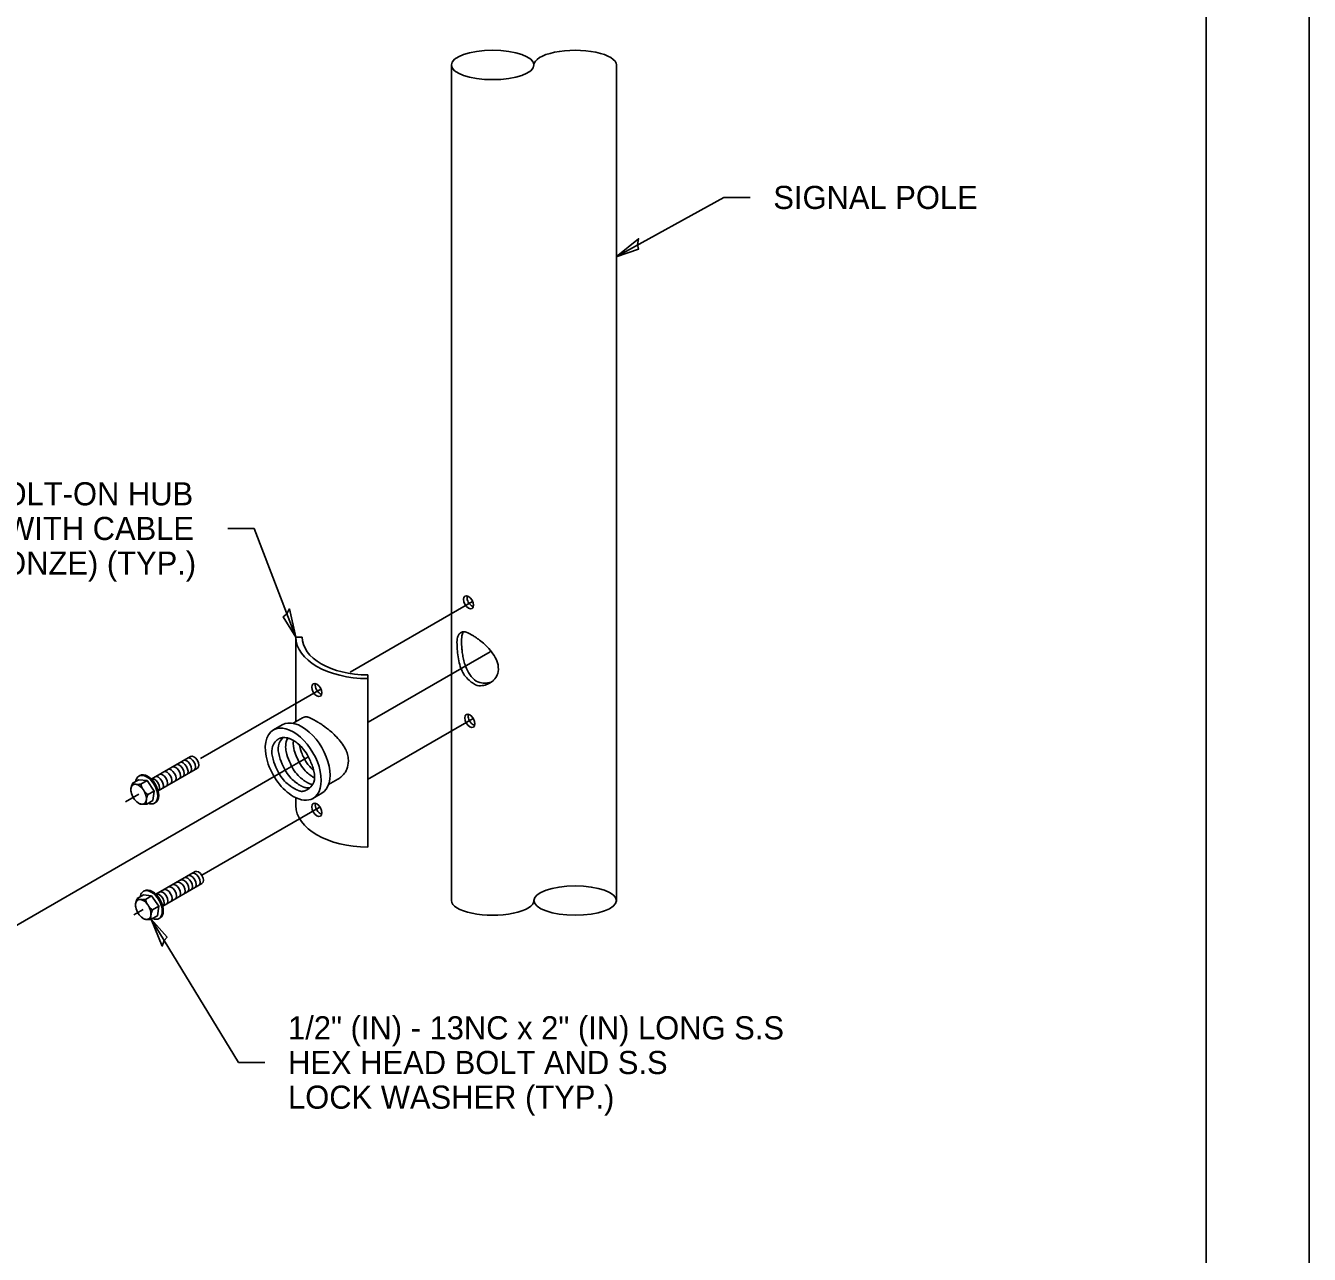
# Model space of a CAD drawing. Extents: x 99999.1 to 100016.1, y 99999.7 to 100010.7.
# Drawn here: x 100012.175 to 100016.062, y 100003.419 to 100007.14 of the extents above; entities that cross this region are included whole.
import ezdxf

# ---------------------------------------------------------------- set-up
doc = ezdxf.new("R2010")
doc.units = 0
for name, color, linetype in [('Level 15', 7, 'Continuous'), ('Level 2', 7, 'Continuous'), ('Level 20', 7, 'Continuous'), ('SH_GI_PlotLimits', 7, 'Continuous'), ('SH_GI_SheetBorder', 7, 'Continuous')]:
    doc.layers.add(name, color=color, linetype=linetype)

msp = doc.modelspace()

# ---------------------------------------------------------------- linework, layer by layer
at = {"layer": 'Level 15'}
for p, q in [((100013.963, 100006.4396), (100014.2892, 100006.6198)), ((100014.3692, 100006.6198), (100014.2892, 100006.6198)), ((100012.7872, 100005.6172), (100012.8672, 100005.6172)), ((100012.993, 100005.2884), (100012.8672, 100005.6172)), ((100013.5286, 100005.3962), (100013.1572, 100005.1818)), ((100013.5813, 100005.2435), (100013.2122, 100005.0304)), ((100013.5302, 100005.0419), (100013.2102, 100004.8571)), ((100013.0292, 100004.9248), (100012.9521, 100004.8802)), ((100012.9536, 100004.8809), (100012.0572, 100004.3633)), ((100012.5554, 100004.4334), (100012.8192, 100003.9999)), ((100012.8992, 100003.9998), (100012.8192, 100003.9998))]:
    msp.add_line(p, q, dxfattribs=at)
for points in [[(100013.963, 100006.4396), (100014.0311, 100006.4944), (100014.0279, 100006.4771), (100014.0311, 100006.4635)], [(100012.993, 100005.2884), (100012.9543, 100005.3493), (100012.9652, 100005.358), (100012.9734, 100005.3736)], [(100012.5554, 100004.4334), (100012.6033, 100004.3794), (100012.5939, 100004.369), (100012.5883, 100004.3524)]]:
    msp.add_lwpolyline(points, close=True, dxfattribs=at)
at = {"layer": 'Level 2'}
for p, q in [((100013.4642, 100005.6753), (100013.4642, 100007.0209)), ((100013.9642, 100004.4871), (100013.9642, 100007.0209)), ((100013.9642, 100004.809), (100013.9642, 100005.9662)), ((100013.4642, 100004.4901), (100013.4642, 100005.6753)), ((100013.5158, 100005.3937), (100013.5158, 100005.3937)), ((100012.993, 100005.0317), (100012.993, 100005.2884)), ((100013.0119, 100005.2884), (100012.993, 100005.2884)), ((100013.2109, 100005.1626), (100013.2109, 100005.1735)), ((100013.2109, 100005.1626), (100013.2109, 100004.6524)), ((100012.7043, 100004.9203), (100013.0683, 100005.1305)), ((100013.0129, 100005.0432), (100012.9851, 100005.0271)), ((100012.952, 100005.0226), (100012.9253, 100005.0071)), ((100012.6742, 100004.9269), (100012.5552, 100004.8582)), ((100012.576, 100004.8223), (100012.6949, 100004.891)), ((100012.5173, 100004.8562), (100012.4988, 100004.8455)), ((100012.5173, 100004.8562), (100012.5424, 100004.8535)), ((100012.5205, 100004.869), (100012.5175, 100004.8673)), ((100012.5424, 100004.8535), (100012.5239, 100004.8427)), ((100012.5424, 100004.8535), (100012.5637, 100004.8219)), ((100013.0922, 100004.8415), (100013.1201, 100004.8575)), ((100012.477, 100004.7891), (100012.5171, 100004.8122)), ((100012.494, 100004.8206), (100012.4943, 100004.8193)), ((100012.5637, 100004.8219), (100012.5452, 100004.8112)), ((100012.5637, 100004.8219), (100012.56, 100004.7932)), ((100012.993, 100004.7782), (100012.993, 100004.8015)), ((100013.045, 100004.7997), (100013.0718, 100004.8151)), ((100012.5118, 100004.7889), (100012.5133, 100004.7877)), ((100012.56, 100004.7932), (100012.5414, 100004.7824)), ((100012.565, 100004.7851), (100012.568, 100004.7868)), ((100012.708, 100004.5672), (100013.0633, 100004.7723)), ((100012.6882, 100004.5778), (100012.5692, 100004.5091)), ((100012.5899, 100004.4732), (100012.7089, 100004.5419)), ((100012.5313, 100004.5072), (100012.5128, 100004.4964)), ((100012.5313, 100004.5072), (100012.5564, 100004.5044)), ((100012.5345, 100004.5199), (100012.5315, 100004.5182)), ((100012.5564, 100004.5044), (100012.5378, 100004.4937)), ((100012.5564, 100004.5044), (100012.5777, 100004.4728)), ((100012.5025, 100004.4465), (100012.5311, 100004.463)), ((100012.508, 100004.4715), (100012.5082, 100004.4702)), ((100012.5777, 100004.4728), (100012.5592, 100004.4621)), ((100012.5777, 100004.4728), (100012.574, 100004.4441)), ((100012.5258, 100004.4399), (100012.5272, 100004.4386)), ((100012.574, 100004.4441), (100012.5554, 100004.4334)), ((100012.579, 100004.436), (100012.582, 100004.4378))]:
    msp.add_line(p, q, dxfattribs=at)
for centre, major_axis, ratio in [((100013.5892, 100007.0209), (0.125, 0), 0.35551), ((100013.5158, 100005.3937), (-0.0109, 0.0188), 0.57735), ((100013.0565, 100005.1278), (-0.0109, 0.0188), 0.57735), ((100013.52, 100005.0345), (-0.0109, 0.0188), 0.57735), ((100013.0565, 100004.765), (-0.0109, 0.0188), 0.57735), ((100013.8392, 100004.4901), (-0.125, 0), 0.35551)]:
    msp.add_ellipse(centre, major_axis=major_axis, ratio=ratio, dxfattribs=at)
for centre, major_axis, ratio, start_param, end_param in [((100013.8392, 100007.0209), (0.125, 0), 0.35551, 6.283185, 9.424778), ((100013.2109, 100005.2884), (0.2179, 0), 0.57735, 3.141593, 4.712389), ((100013.2109, 100005.2884), (-0.199, 0), 0.57735, 0, 1.570796), ((100013.067, 100005.134), (-0.0109, 0.0188), 0.57735, 0.514135, 2.639462), ((100013.0119, 100004.9188), (0.0599, -0.1037), 0.577347, 0, 3.141593), ((100012.9852, 100004.9034), (0.0599, -0.1037), 0.577347, 3.141593, 5.497785), ((100012.9852, 100004.9034), (0.0599, -0.1037), 0.577347, 0, 3.141593), ((100012.6629, 100004.8964), (-0.0104, 0.0179), 0.57735, 3.141593, 6.283185), ((100012.675, 100004.9034), (-0.0104, 0.0179), 0.57735, 3.141593, 6.283185), ((100012.6846, 100004.9089), (-0.0104, 0.0179), 0.57735, 3.141593, 6.283185), ((100012.6033, 100004.862), (-0.0104, 0.0179), 0.57735, 3.141593, 6.283185), ((100012.6156, 100004.8691), (-0.0104, 0.0179), 0.57735, 3.141593, 6.283185), ((100012.6292, 100004.8764), (-0.0104, 0.0179), 0.57735, 3.141593, 6.283185), ((100012.6407, 100004.8836), (-0.0104, 0.0179), 0.57735, 3.141593, 6.283185), ((100012.6519, 100004.8901), (-0.0104, 0.0179), 0.57735, 3.141593, 6.283185), ((100012.5171, 100004.8122), (0.0166, -0.0287), 0.57735, 2.740181, 3.787378), ((100012.5413, 100004.8262), (-0.0237, 0.0411), 0.57735, 0.547329, 0.642761), ((100012.5171, 100004.8122), (-0.0166, 0.0287), 0.57735, 4.834576, 5.881773), ((100012.5413, 100004.8262), (-0.0237, 0.0411), 0.57735, 6.283185, 6.830515), ((100012.5413, 100004.8262), (-0.0237, 0.0411), 0.57735, 3.141593, 6.283185), ((100012.5443, 100004.8279), (-0.0237, 0.0411), 0.57735, 3.141593, 6.283185), ((100012.5656, 100004.8402), (-0.0104, 0.0179), 0.57735, 3.141593, 6.283185), ((100012.5772, 100004.8469), (-0.0104, 0.0179), 0.57735, 3.141593, 6.283185), ((100012.5897, 100004.8541), (-0.0104, 0.0179), 0.57735, 3.141593, 6.283185), ((100012.5171, 100004.8122), (-0.0166, 0.0287), 0.57735, 0.645786, 1.013198), ((100012.5171, 100004.8122), (-0.0166, 0.0287), 0.57735, 1.013198, 1.692983), ((100012.5171, 100004.8122), (-0.0166, 0.0287), 0.57735, 3.787378, 4.834576), ((100012.9852, 100004.9034), (0.0599, -0.1037), 0.577347, 5.497785, 6.283185), ((100012.5171, 100004.8122), (-0.0166, 0.0287), 0.57735, 1.692983, 2.128395), ((100012.5171, 100004.8122), (-0.0166, 0.0287), 0.57735, 2.128395, 2.740181), ((100012.5171, 100004.8122), (-0.0166, 0.0287), 0.57735, 2.740181, 3.787378), ((100012.5413, 100004.8262), (-0.0237, 0.0411), 0.57735, 2.498832, 3.141593), ((100013.2109, 100004.7782), (-0.2179, 0), 0.57735, 0, 1.570796), ((100013.067, 100004.7714), (-0.0109, 0.0188), 0.57735, 0.514135, 2.639462), ((100012.6768, 100004.5473), (-0.0104, 0.0179), 0.57735, 3.141593, 6.283185), ((100012.689, 100004.5544), (-0.0104, 0.0179), 0.57735, 3.141593, 6.283185), ((100012.6985, 100004.5599), (-0.0104, 0.0179), 0.57735, 3.141593, 6.283185), ((100012.5582, 100004.4789), (-0.0237, 0.0411), 0.57735, 3.141593, 6.283185), ((100012.6172, 100004.5129), (-0.0104, 0.0179), 0.57735, 3.141593, 6.283185), ((100012.6296, 100004.52), (-0.0104, 0.0179), 0.57735, 3.141593, 6.283185), ((100012.6431, 100004.5274), (-0.0104, 0.0179), 0.57735, 3.141593, 6.283185), ((100012.6547, 100004.5345), (-0.0104, 0.0179), 0.57735, 3.141593, 6.283185), ((100012.6659, 100004.541), (-0.0104, 0.0179), 0.57735, 3.141593, 6.283185), ((100012.5311, 100004.4632), (0.0166, -0.0287), 0.57735, 2.740181, 3.787378), ((100012.5552, 100004.4771), (-0.0237, 0.0411), 0.57735, 0.547329, 0.642761), ((100012.5311, 100004.4632), (-0.0166, 0.0287), 0.57735, 4.834576, 5.881773), ((100012.5552, 100004.4771), (-0.0237, 0.0411), 0.57735, 6.283185, 6.830515), ((100012.5552, 100004.4771), (-0.0237, 0.0411), 0.57735, 3.141593, 6.283185), ((100012.5796, 100004.4912), (-0.0104, 0.0179), 0.57735, 3.141593, 6.283185), ((100012.5911, 100004.4979), (-0.0104, 0.0179), 0.57735, 3.141593, 6.283185), ((100012.6036, 100004.5051), (-0.0104, 0.0179), 0.57735, 3.141593, 6.283185), ((100013.5892, 100004.4901), (-0.125, 0), 0.35551, 6.283185, 9.424778), ((100012.5311, 100004.4632), (-0.0166, 0.0287), 0.57735, 0.645786, 1.013198), ((100012.5311, 100004.4632), (-0.0166, 0.0287), 0.57735, 1.013198, 1.692983), ((100012.5311, 100004.4632), (-0.0166, 0.0287), 0.57735, 1.692983, 2.128395), ((100012.5311, 100004.4632), (-0.0166, 0.0287), 0.57735, 3.787378, 4.834576), ((100012.5311, 100004.4632), (-0.0166, 0.0287), 0.57735, 2.128395, 2.740181), ((100012.5311, 100004.4632), (-0.0166, 0.0287), 0.57735, 2.740181, 3.787378), ((100012.5552, 100004.4771), (-0.0237, 0.0411), 0.57735, 2.498832, 3.141593)]:
    msp.add_ellipse(centre, major_axis=major_axis, ratio=ratio, start_param=start_param, end_param=end_param, dxfattribs=at)
for points, degree in [([(100013.5307, 100005.3807), (100013.528, 100005.3813), (100013.5188, 100005.3859), (100013.5111, 100005.4018), (100013.5114, 100005.4111), (100013.5118, 100005.4131)], 3), ([(100013.5803, 100005.1484), (100013.5771, 100005.1466), (100013.5723, 100005.1445), (100013.5526, 100005.139), (100013.5334, 100005.1435), (100013.5015, 100005.1707), (100013.4869, 100005.2073), (100013.4803, 100005.2616), (100013.4816, 100005.2853), (100013.4862, 100005.2949), (100013.4875, 100005.2971), (100013.4889, 100005.2988), (100013.4904, 100005.3003), (100013.4915, 100005.301), (100013.492, 100005.3013)], 3), ([(100013.492, 100005.3013), (100013.4995, 100005.3057), (100013.5122, 100005.3024), (100013.5289, 100005.2928)], 2), ([(100013.4997, 100005.3032), (100013.4994, 100005.3026), (100013.4987, 100005.3013), (100013.4967, 100005.2957), (100013.4955, 100005.288), (100013.495, 100005.2766), (100013.495, 100005.2703), (100013.4954, 100005.2591), (100013.4962, 100005.2491), (100013.4983, 100005.2336), (100013.5014, 100005.2167), (100013.5068, 100005.2003), (100013.5186, 100005.1736), (100013.5383, 100005.1523), (100013.5627, 100005.1482), (100013.5722, 100005.1488), (100013.5764, 100005.1495), (100013.5805, 100005.1505), (100013.5839, 100005.1515), (100013.5858, 100005.1523), (100013.5864, 100005.1526)], 3), ([(100013.5289, 100005.2928), (100013.5303, 100005.292), (100013.533, 100005.2904), (100013.5385, 100005.2869), (100013.5442, 100005.283), (100013.5616, 100005.2699), (100013.5777, 100005.2549), (100013.5947, 100005.2316), (100013.6054, 100005.2117), (100013.608, 100005.1822), (100013.5982, 100005.1637), (100013.5894, 100005.155), (100013.5861, 100005.1523), (100013.5831, 100005.1501), (100013.581, 100005.1489), (100013.5803, 100005.1484)], 3), ([(100013.0569, 100005.0323), (100013.0365, 100005.044), (100013.0214, 100005.0482), (100013.0129, 100005.0432)], 2), ([(100013.5348, 100005.0213), (100013.532, 100005.0218), (100013.5226, 100005.0264), (100013.5147, 100005.0427), (100013.5151, 100005.052), (100013.5155, 100005.054)], 3), ([(100013.1201, 100004.8575), (100013.1223, 100004.8588), (100013.1284, 100004.8629), (100013.1413, 100004.8747), (100013.1505, 100004.892), (100013.1542, 100004.9201), (100013.1441, 100004.9538), (100013.1117, 100004.9923), (100013.084, 100005.0146), (100013.0696, 100005.0243), (100013.0669, 100005.0262), (100013.0642, 100005.0278), (100013.0617, 100005.0294), (100013.0593, 100005.0309), (100013.0577, 100005.0318), (100013.0569, 100005.0323)], 3), ([(100012.941, 100004.9798), (100012.9404, 100004.9794), (100012.9384, 100004.9783), (100012.9356, 100004.9758), (100012.9201, 100004.9599), (100012.9195, 100004.9266), (100012.9335, 100004.8926), (100012.9436, 100004.8707), (100012.9593, 100004.8507), (100012.9744, 100004.8386), (100012.9771, 100004.8366), (100012.9798, 100004.8347), (100012.9825, 100004.8329), (100012.9843, 100004.8319), (100012.9852, 100004.8313)], 3), ([(100012.9539, 100004.9838), (100012.9531, 100004.983), (100012.9393, 100004.9682), (100012.9387, 100004.9356), (100012.9527, 100004.9016), (100012.9628, 100004.8796), (100012.9784, 100004.8597), (100012.9936, 100004.8476), (100012.9963, 100004.8455), (100012.999, 100004.8437), (100013.0016, 100004.8419), (100013.0034, 100004.8408), (100013.0043, 100004.8403)], 3), ([(100013.0293, 100004.827), (100013.0306, 100004.8277), (100013.0336, 100004.8299), (100013.0502, 100004.8457), (100013.0508, 100004.8814), (100013.0343, 100004.92), (100013.0251, 100004.937), (100013.0086, 100004.9581), (100012.9933, 100004.9708), (100012.9833, 100004.9765), (100012.9797, 100004.9784), (100012.976, 100004.98), (100012.9724, 100004.9813), (100012.9636, 100004.9839), (100012.9561, 100004.9844), (100012.9493, 100004.9831), (100012.9471, 100004.9825), (100012.945, 100004.9818), (100012.943, 100004.9809), (100012.9417, 100004.9802), (100012.941, 100004.9798)], 3), ([(100012.9684, 100004.9825), (100012.9608, 100004.9663), (100012.9619, 100004.9398), (100012.9741, 100004.91), (100012.9842, 100004.8881), (100012.9999, 100004.8681), (100013.015, 100004.856), (100013.0177, 100004.854), (100013.0204, 100004.8521), (100013.0231, 100004.8503), (100013.0249, 100004.8493), (100013.0258, 100004.8487)], 3), ([(100012.9856, 100004.9752), (100012.9848, 100004.9615), (100012.9877, 100004.9443), (100012.9962, 100004.9237), (100013.0063, 100004.9017), (100013.0219, 100004.8818), (100013.0371, 100004.8697), (100013.0398, 100004.8676), (100013.0424, 100004.8657), (100013.0451, 100004.864), (100013.0469, 100004.8629), (100013.0478, 100004.8624)], 3), ([(100013.004, 100004.9612), (100013.0054, 100004.9536), (100013.0079, 100004.9446), (100013.0131, 100004.9321), (100013.0221, 100004.9125), (100013.0347, 100004.8956), (100013.0459, 100004.8851)], 3), ([(100012.4988, 100004.8455), (100012.4964, 100004.8399), (100012.4945, 100004.8343), (100012.4939, 100004.8294)], 2), ([(100012.5083, 100004.8424), (100012.504, 100004.8428), (100012.5009, 100004.844), (100012.4988, 100004.8455)], 2), ([(100012.5239, 100004.8427), (100012.5181, 100004.8421), (100012.5126, 100004.8419), (100012.5083, 100004.8424)], 2), ([(100012.5315, 100004.8252), (100012.5278, 100004.8307), (100012.5254, 100004.8367), (100012.5239, 100004.8427)], 2), ([(100013.0043, 100004.8403), (100013.0153, 100004.8339), (100013.0262, 100004.8311), (100013.0356, 100004.8319)], 2), ([(100013.0258, 100004.8487), (100013.0314, 100004.8455), (100013.0371, 100004.8431), (100013.0425, 100004.8417)], 2), ([(100012.4939, 100004.8294), (100012.4934, 100004.8261), (100012.4935, 100004.8232), (100012.494, 100004.8206)], 2), ([(100012.5452, 100004.8112), (100012.54, 100004.8151), (100012.5352, 100004.8198), (100012.5315, 100004.8252)], 2), ([(100012.5403, 100004.7951), (100012.5409, 100004.8), (100012.5428, 100004.8056), (100012.5452, 100004.8112)], 2), ([(100012.9852, 100004.8313), (100013.0015, 100004.8218), (100013.0178, 100004.8202), (100013.0293, 100004.827)], 2), ([(100012.5133, 100004.7877), (100012.5143, 100004.7868), (100012.5153, 100004.786), (100012.5163, 100004.7852)], 2), ([(100012.5163, 100004.7852), (100012.5185, 100004.7837), (100012.5215, 100004.7825), (100012.5259, 100004.7821)], 2), ([(100012.5259, 100004.7821), (100012.5302, 100004.7816), (100012.5357, 100004.7818), (100012.5414, 100004.7824)], 2), ([(100012.5414, 100004.7824), (100012.5402, 100004.7859), (100012.5396, 100004.7901), (100012.5403, 100004.7951)], 2), ([(100012.5128, 100004.4964), (100012.5104, 100004.4909), (100012.5085, 100004.4853), (100012.5079, 100004.4803)], 2), ([(100012.5223, 100004.4933), (100012.5179, 100004.4938), (100012.5149, 100004.495), (100012.5128, 100004.4964)], 2), ([(100012.5378, 100004.4937), (100012.5321, 100004.4931), (100012.5266, 100004.4928), (100012.5223, 100004.4933)], 2), ([(100012.5455, 100004.4762), (100012.5418, 100004.4816), (100012.5394, 100004.4876), (100012.5378, 100004.4937)], 2), ([(100012.5079, 100004.4803), (100012.5074, 100004.4771), (100012.5075, 100004.4741), (100012.508, 100004.4715)], 2), ([(100012.5592, 100004.4621), (100012.554, 100004.4661), (100012.5491, 100004.4707), (100012.5455, 100004.4762)], 2), ([(100012.5543, 100004.446), (100012.5549, 100004.451), (100012.5568, 100004.4565), (100012.5592, 100004.4621)], 2), ([(100012.5272, 100004.4386), (100012.5282, 100004.4378), (100012.5293, 100004.437), (100012.5303, 100004.4361)], 2), ([(100012.5303, 100004.4361), (100012.5325, 100004.4347), (100012.5355, 100004.4335), (100012.5398, 100004.433)], 2), ([(100012.5398, 100004.433), (100012.5441, 100004.4325), (100012.5496, 100004.4328), (100012.5554, 100004.4334)], 2), ([(100012.5554, 100004.4334), (100012.5542, 100004.4369), (100012.5536, 100004.441), (100012.5543, 100004.446)], 2)]:
    msp.add_open_spline(points, degree=degree, dxfattribs=at)
at = {"layer": 'SH_GI_PlotLimits'}
msp.add_lwpolyline([(99999.0625, 99999.6875), (100016.0625, 99999.6875), (100016.0625, 100010.6875), (99999.0625, 100010.6875)], close=True, dxfattribs=at)
at = {"layer": 'SH_GI_SheetBorder'}
msp.add_line((100015.75, 100010.375), (100015.75, 100000), dxfattribs=at)

# ---------------------------------------------------------------- texts
at = {"layer": 'Level 20'}
for s, p in [('SIGNAL POLE', (100014.4392, 100006.5848)), ('CURVED BOLT-ON HUB', (100011.6212, 100005.6872)), ('PLATE WITH CABLE', (100011.7901, 100005.5822)), ('GUIDE (BRONZE) (TYP.)', (100011.6199, 100005.4772)), ('1/2" (IN) - 13NC x 2" (IN) LONG S.S ', (100012.9695, 100004.0698)), ('HEX HEAD BOLT AND S.S', (100012.9695, 100003.9648)), ('LOCK WASHER (TYP.)', (100012.9695, 100003.8598))]:
    msp.add_text(s, height=0.07, dxfattribs=at).set_placement(p)

doc.saveas('drawing.dxf')
